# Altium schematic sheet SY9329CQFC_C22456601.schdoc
size 127 x 101 mm
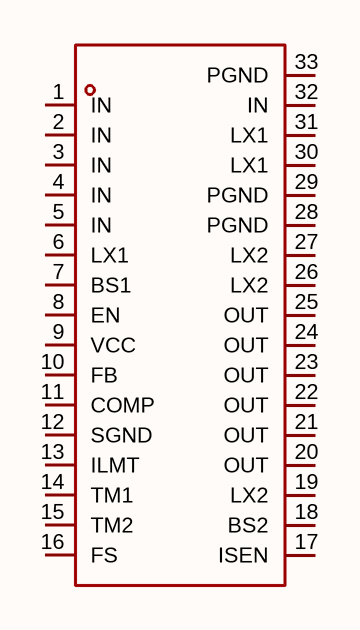
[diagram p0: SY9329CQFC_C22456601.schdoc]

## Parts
U?  sy9329cqfc_c22456601  [QFN-32_L4.0-W4.0-P0.40-BL-EP_SY9329CQFC]  (value not drawn)

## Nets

Not connected (* = marked no-connect by the designer): U? 1(IN) 2(IN) 3(IN) 4(IN) 5(IN) 6(LX1) 7(BS1) 8(EN) 9(VCC) 10(FB) 11(COMP) 12(SGND) 13(ILMT) 14(TM1) 15(TM2) 16(FS) 17(ISEN) 18(BS2) 19(LX2) 20(OUT) 21(OUT) 22(OUT) 23(OUT) 24(OUT) 25(OUT) 26(LX2) 27(LX2) 28(PGND) 29(PGND) 30(LX1) 31(LX1) 32(IN) 33(PGND)

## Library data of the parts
U? = sy9329cqfc_c22456601: 功能类型:升降压型;工作电压:4V~28V;输出电压:-;输出电流:-;输出类型:可调;; Manufacturer: Silergy(矽力杰); AddInBom: yes; ModelId: 295f78e9cf404df5a751033a9ad33a07; ModelTransform: 158.267,158.267,0,0,0,0,0,0,0; Function: 升降压型; Voltage - Supply: 4V~28V; Frequency - Switching: 500kHz；250kHz; Synchronous Rectifier: 是; Number of Outputs: 1; Topology: 降压-升压式; Quiescent Current: 300uA; Switch tube (built-in/external): 内置; Output Type: 可调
